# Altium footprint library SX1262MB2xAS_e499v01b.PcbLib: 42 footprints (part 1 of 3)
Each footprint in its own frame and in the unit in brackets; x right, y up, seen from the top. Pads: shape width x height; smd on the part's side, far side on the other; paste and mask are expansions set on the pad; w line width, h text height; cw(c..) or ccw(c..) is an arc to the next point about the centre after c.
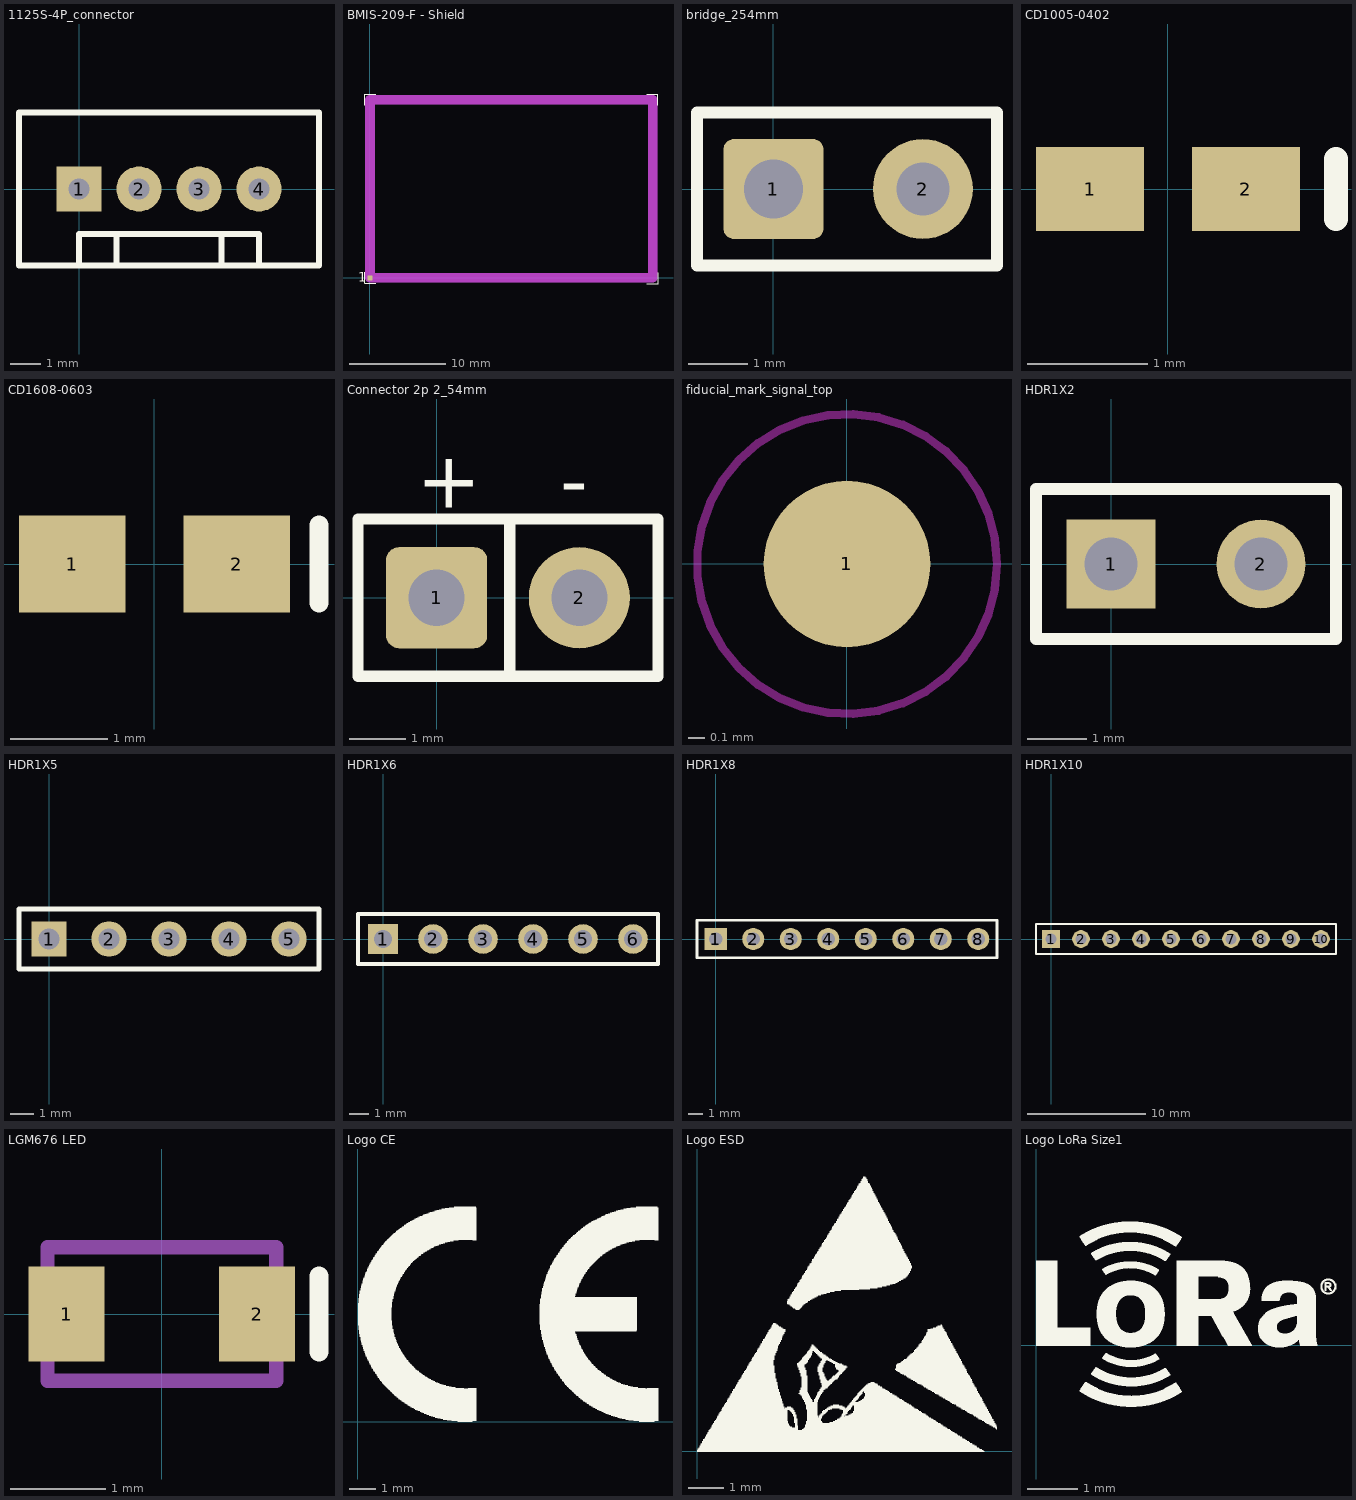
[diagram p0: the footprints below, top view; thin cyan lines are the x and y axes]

## 1125S-4P_connector [mm] "Connector; Header; 4 Position; P/N: 1125S-4P; Manuf: TAIFENG"
pads (4):
  rect 1.5x1.5 hole 0.7 mask+0.05: 1(0,0)
  round 1.5 hole 0.7 mask+0.05: 2(2,0) 3(4,0) 4(6,0)
Top Overlay:
  lines w0.2: 0,-2.55 0,-1.5 6,-1.5 6,-2.55 ; 1.25,-2.55 1.25,-1.5 ; 4.75,-2.55 4.75,-1.5 ; -2,-2.55 8,-2.55 8,2.55 -2,2.55 -2,-2.55
3D body: height 2.95, standoff 0, extent -2,-2.55 8,2.55

## BMIS-209-F - Shield [mm] "BMIS-209-F EMI Gasket - modif SolderMask - Standard Surface Mount Shields -  Laird Technologies"
height 6.5
pads (1):
  rect 0.5x0.5 smd paste-1 mask+0.05: 1(0,0)
Top Overlay:
  lines w0.1: -0.55,0.6 -0.55,-0.55 0.6,-0.55 ; -0.55,18 -0.55,19.15 0.6,19.15 ; 28.9,-0.6 30.05,-0.6 30.05,0.55 ; 28.9,19.15 30.05,19.15 30.05,18
  text "1" at -1.25,-0.4 h1
Top Paste:
  region: 4.35,19 4.35,18 -0.4,18 -0.4,19
  region: 7.1,19 10.3,19 10.3,18 7.1,18
  region: 13.1,19 16.35,19 16.35,18 13.1,18
  region: 19.1,19 22.3,19 22.3,18 19.1,18
  region: 25.1,19 29.9,19 29.9,18 25.1,18
  region: 28.9,4.85 29.9,4.85 29.9,-0.45 28.9,-0.45
  region: 28.9,10.85 29.9,10.85 29.9,7.65 28.9,7.65
  region: 28.9,13.65 28.9,18.95 29.9,18.95 29.9,13.65
  region: -0.4,13.7 -0.4,19 0.6,19 0.6,13.7
  region: -0.4,10.9 0.6,10.9 0.6,7.7 -0.4,7.7
  region: -0.4,4.6 0.6,4.6 0.6,-0.4 -0.4,-0.4
  region: 25.1,0.55 29.9,0.55 29.9,-0.45 25.1,-0.45
  region: 19.1,0.6 22.3,0.6 22.3,-0.4 19.1,-0.4
  region: 13.1,0.6 16.35,0.6 16.35,-0.4 13.1,-0.4
  region: 7.1,0.6 10.3,0.6 10.3,-0.4 7.1,-0.4
  region: 4.35,0.6 4.35,-0.4 -0.4,-0.4 -0.4,0.6
Top Solder:
  region: 28.9,13.65 28.9,18.95 29.9,18.95 29.9,13.65
  region: 28.9,7.65 28.9,10.85 29.9,10.85 29.9,7.65
  region: 28.9,-0.45 28.9,4.85 29.9,4.85 29.9,-0.45
  region: -0.4,-0.4 -0.4,4.6 0.6,4.6 0.6,-0.4
  region: -0.4,7.7 -0.4,10.9 0.6,10.9 0.6,7.7
  region: -0.4,13.7 -0.4,19 0.6,19 0.6,13.7
  region: 4.35,-0.4 -0.4,-0.4 -0.4,0.6 4.35,0.6
  region: 10.3,-0.4 7.1,-0.4 7.1,0.6 10.3,0.6
  region: 16.35,-0.4 13.1,-0.4 13.1,0.6 16.35,0.6
  region: 29.9,-0.45 25.1,-0.45 25.1,0.55 29.9,0.55
  region: 22.3,-0.4 19.1,-0.4 19.1,0.6 22.3,0.6
  region: 22.3,18 19.1,18 19.1,19 22.3,19
  region: 29.9,18 25.1,18 25.1,19 29.9,19
  region: 16.35,18 13.1,18 13.1,19 16.35,19
  region: 10.3,18 7.1,18 7.1,19 10.3,19
  region: 4.35,18 -0.4,18 -0.4,19 4.35,19
Mechanical 15 keep-out:
  lines w1: 0,0 29.5,0 29.5,18.6 0,18.6 0,0
3D body: height 0.8, standoff 0.2, extent -0.3,-0.3 0.3,0.3

## bridge_254mm [mm] "Generic Bridge 2.54mm, 2 Leads 0.9mm;"
height 1
pads (2):
  rrect20% 1.7x1.7 hole 1 paste+0 mask+0.05: 1(0,0)
  round 1.7 hole 0.9 paste+0 mask+0.05: 2(2.54,0)
Top Overlay:
  lines w0.2: -1.3,-1.3 -1.3,1.3 3.8,1.3 3.8,-1.3 -1.3,-1.3

## CD1005-0402 [mm] "Chip Diode; Body 1.0 x 0.5 mm (LxW typ)"
height 0.6
pads (2):
  rect 0.9x0.7 smd mask+0.05: 1(-0.65,0) 2(0.65,0)
Top Overlay:
  lines w0.2: 1.4,-0.25 1.4,0.25

## CD1608-0603 [mm] "Chip Diode; Body 1.6 x 0.8 mm (LxW typ)"
height 0.85
pads (2):
  rect 1.1x1 smd mask+0.05: 1(-0.85,0) 2(0.85,0)
Top Overlay:
  lines w0.2: 1.7,-0.4 1.7,0.4

## Connector 2p 2_54mm [mm] "Generic connector 2.54mm, 2 Leads 1mm;"
height 1
pads (2):
  rrect25% 1.8x1.8 hole 1 paste+0 mask+0.05: 1(0,0)
  round 1.8 hole 1 paste+0 mask+0.05: 2(2.54,0)
Top Overlay:
  lines w0.2: 1.3,-1.4 1.3,1.4 ; -1.4,-1.4 3.94,-1.4 3.94,1.4 -1.4,1.4 -1.4,-1.4
  text "+" at -0.35,1.6 h1
  text "-" at 2.2,1.6 h1

## fiducial_mark_signal_top [mm] "Fiducial mark for automatic assembly"
height 1
pads (1):
  round 1 smd paste-2 mask+0.5: 1(0,0)
Top Layer keep-out:
  circle w0.05: c0,0 r0.9

## HDR1X2 [mm] "Connector; Header; 2 Position"
pads (2):
  rect 1.5x1.5 hole 0.9: 1(0,0)
  round 1.5 hole 0.9: 2(2.54,0)
Top Overlay:
  lines w0.2: -1.27,-1.27 -1.27,1.27 3.81,1.27 3.81,-1.27 -1.27,-1.27

## HDR1X5 [mm] "Connector; Header; 5 Position"
pads (5):
  rect 1.5x1.5 hole 0.9: 1(0,0)
  round 1.5 hole 0.9: 2(2.54,0) 3(5.08,0) 4(7.62,0) 5(10.16,0)
Top Overlay:
  lines w0.2: -1.27,-1.27 11.43,-1.27 11.43,1.27 -1.27,1.27 -1.27,-1.27

## HDR1X6 [mm] "Connector; Header; 6 Position"
pads (6):
  rect 1.5x1.5 hole 0.9: 1(0,0)
  round 1.5 hole 0.9: 2(2.54,0) 3(5.08,0) 4(7.62,0) 5(10.16,0) 6(12.7,0)
Top Overlay:
  lines w0.2: -1.27,-1.27 13.97,-1.27 13.97,1.27 -1.27,1.27 -1.27,-1.27

## HDR1X8 [mm] "Connector; Header; 8 Position"
pads (8):
  rect 1.5x1.5 hole 0.9: 1(0,0)
  round 1.5 hole 0.9: 2(2.54,0) 3(5.08,0) 4(7.62,0) 5(10.16,0) 6(12.7,0) 7(15.24,0) 8(17.78,0)
Top Overlay:
  lines w0.2: -1.27,-1.27 -1.27,1.27 19.05,1.27 19.05,-1.27 -1.27,-1.27

## HDR1X10 [mm] "Connector; Header; 10 Position"
pads (10):
  rect 1.5x1.5 hole 0.9: 1(0,0)
  round 1.5 hole 0.9: 2(2.54,0) 3(5.08,0) 4(7.62,0) 5(10.16,0) 6(12.7,0) 7(15.24,0) 8(17.78,0) 9(20.32,0) 10(22.86,0)
Top Overlay:
  lines w0.2: -1.27,-1.27 -1.27,1.27 0.635,1.27 24.13,1.27 24.13,-1.27 -1.27,-1.27

## LGM676 LED [mm] "Chip Diode; Body 2.1 x 1.4 mm (LxW typ)"
height 1.1
pads (2):
  rect 0.8x1 smd mask+0.05: 1(-1,0) 2(1,0)
Top Overlay:
  lines w0.2: 1.65,-0.4 1.65,0.4
Mechanical 15:
  lines w0.15: -1.2,-0.7 1.2,-0.7 1.2,0.7 -1.2,0.7 -1.2,-0.7
3D body: height 12, standoff 0, extent -1.2,-0.7 1.2,0.7

## Logo CE [mm] "Logo CE"
height 0.1
Top Overlay:
  drawing of 654 lines, arcs and shapes, not listed

## Logo ESD [mm] "Logo ESD"
height 0.1
Top Overlay:
  drawing of 682 lines, arcs and shapes, not listed

## Logo LoRa Size1 [mm] "Logo LoRa Size1 - Top Overlay - 6x4mm - Registered"
Top Overlay:
  drawing of 1298 lines, arcs and shapes, not listed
